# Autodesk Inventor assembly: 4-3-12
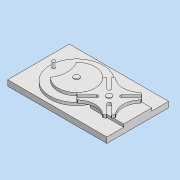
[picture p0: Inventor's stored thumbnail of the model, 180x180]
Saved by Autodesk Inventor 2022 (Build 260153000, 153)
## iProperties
Created: 2021-07
Part Number: 4-3-12
Document SubType Name: Assembly
Designer: DesignLab
Author: DesignLab
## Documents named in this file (5)
- d:\Users\DesignLab\Desktop\ver2022\ch04\4-3-12.iam
- d:\Users\DesignLab\Desktop\ver2022\ch04\03-ベース板_完成.ipt
- d:\Users\DesignLab\Desktop\ver2022\ch04\01-駆動車_完成.ipt
- d:\Users\DesignLab\Desktop\ver2022\ch04\02-従動車_完成.ipt
- d:\Users\DesignLab\Desktop\ver2022\ch04\04-ピン_完成.ipt
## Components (5 placed, 4 different names)
1. 03-ベース板_完成:1 — 回転:1, 回転:2, 駆動車回転
2. 01-駆動車_完成:1 — 回転:1, フラッシュ:1, 駆動車回転
3. 02-従動車_完成:1 — 回転:2, 回転:3
4. 04-ピン_完成:1 — フラッシュ:1
5. 04-ピン_完成:2 — 回転:3
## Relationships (5: RevoluteJoint 3, Flush 1, Angle 1)
- 回転:1 [RevoluteJoint]: 03-ベース板_完成:1 ↔ 01-駆動車_完成:1
- 回転:2 [RevoluteJoint]: 03-ベース板_完成:1 ↔ 02-従動車_完成:1
- フラッシュ:1 [Flush]: 01-駆動車_完成:1 ↔ 04-ピン_完成:1
- 回転:3 [RevoluteJoint]: 02-従動車_完成:1 ↔ 04-ピン_完成:2
- 駆動車回転 [Angle]: 03-ベース板_完成:1 ↔ 01-駆動車_完成:1
